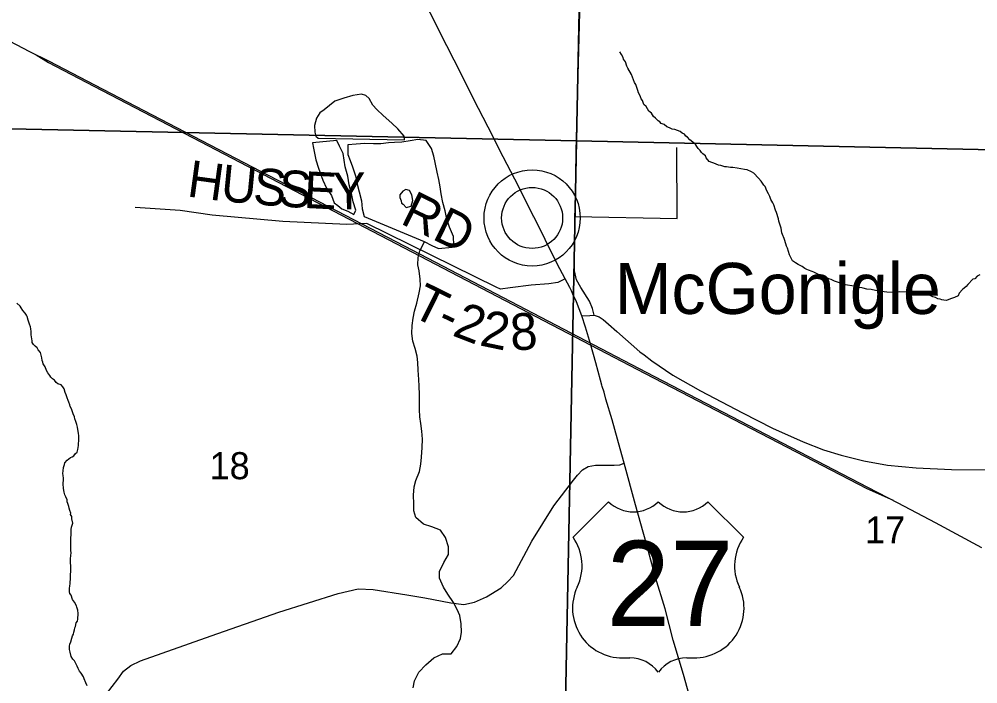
# Model space of a CAD drawing. Extents: x 0 to 34, y 0 to 22.
# Drawn here: x 6.13 to 7.614, y 14.792 to 15.821 of the extents above; entities that cross this region are included whole.
import ezdxf

# ---------------------------------------------------------------- set-up
doc = ezdxf.new("R2010")
doc.units = 0
for name, color, linetype in [('GM_X_County_Road', 7, 'Continuous'), ('GM_X_Minor_Lake', 7, 'Continuous'), ('GM_X_Minor_River', 7, 'Continuous'), ('GM_X_Rail_Line', 7, 'Continuous'), ('GM_X_Section', 7, 'Continuous'), ('GM_X_Section_Text', 7, 'Continuous'), ('GM_X_State_Route', 7, 'Continuous'), ('GM_X_Township_Road', 7, 'Continuous'), ('GM_X_Township_Road_Text', 7, 'Continuous'), ('GM_X_Unincorporated', 7, 'Continuous'), ('GM_X_Unincorporated_Location', 7, 'Continuous'), ('GM_X_Unincorporated_Text', 7, 'Continuous'), ('GM_X_US_Location', 7, 'Continuous'), ('GM_X_US_Route', 7, 'Continuous'), ('GM_X_US_Shield', 7, 'Continuous')]:
    doc.layers.add(name, color=color, linetype=linetype)

msp = doc.modelspace()

# ---------------------------------------------------------------- linework, layer by layer
at = {"layer": 'GM_X_County_Road'}
for points in [[(6.9899, 15.456), (6.9901, 15.4871), (6.9904, 15.5157), (6.9912, 15.5373), (6.9922, 15.6175), (6.9998, 15.8902), (7.0067, 16.3405), (7.0224, 16.9184), (7.0254, 17.1457)], [(7.0201, 15.3628), (7.0177, 15.3733), (7.0128, 15.3849), (6.9998, 15.4057), (6.993, 15.4175), (6.9897, 15.4318), (6.9899, 15.456)], [(6.2653, 14.7771), (6.2832, 14.7997), (6.2917, 14.8121), (6.3034, 14.8208), (6.318, 14.8278), (6.4275, 14.8668), (6.5322, 14.9031), (6.6241, 14.9321), (6.655, 14.9392), (6.6781, 14.9386), (6.7301, 14.9299), (6.7582, 14.9253), (6.7982, 14.9179), (6.8185, 14.9153), (6.8352, 14.9186), (6.8535, 14.9273), (6.8764, 14.941), (6.8868, 14.9508), (6.8953, 14.9601), (6.9238, 15.013), (6.9578, 15.0678), (6.9883, 15.1075), (6.9943, 15.1154), (7.0023, 15.1236), (7.0108, 15.1289), (7.0224, 15.1307), (7.0353, 15.1306), (7.0509, 15.1308), (7.06, 15.1311), (7.0665, 15.1341)]]:
    msp.add_lwpolyline(points, dxfattribs=at)
at = {"layer": 'GM_X_Minor_Lake'}
for points in [[(6.7265, 15.6345), (6.7262, 15.6398), (6.7166, 15.6514), (6.7069, 15.6603), (6.6938, 15.6719), (6.6837, 15.6812), (6.6778, 15.6882), (6.6722, 15.6982), (6.667, 15.7032), (6.6599, 15.7052), (6.6469, 15.7032), (6.6328, 15.6988), (6.619, 15.6941), (6.6106, 15.6875), (6.6021, 15.6808), (6.5956, 15.6763), (6.5905, 15.668), (6.5872, 15.6567), (6.5878, 15.6464), (6.5896, 15.6403), (6.593, 15.6369)], [(6.593, 15.6369), (6.7265, 15.6345)], [(6.6217, 15.6333), (6.5845, 15.6298), (6.5858, 15.6214), (6.5897, 15.6035), (6.5936, 15.5905), (6.6005, 15.5717), (6.606, 15.5595), (6.6137, 15.5483), (6.6177, 15.5369)], [(6.6177, 15.5369), (6.6233, 15.533), (6.6297, 15.5275), (6.6391, 15.5239), (6.6485, 15.5188), (6.6513, 15.5256), (6.6473, 15.5386), (6.6449, 15.5512), (6.641, 15.5646), (6.6389, 15.5783), (6.6347, 15.5928), (6.6316, 15.613), (6.6261, 15.6245), (6.6217, 15.6333)], [(6.757, 15.477), (6.7691, 15.4707), (6.7792, 15.4664), (6.8005, 15.4682), (6.8032, 15.4713), (6.8023, 15.485), (6.7965, 15.4991), (6.7922, 15.5117), (6.7894, 15.5243), (6.7862, 15.5373), (6.7834, 15.551), (6.7817, 15.5617), (6.78, 15.5731), (6.7772, 15.5842), (6.7741, 15.5995), (6.772, 15.609), (6.7684, 15.6212), (6.7603, 15.6335), (6.7474, 15.6349), (6.7356, 15.6328), (6.7226, 15.6308), (6.7112, 15.6302), (6.7017, 15.6296), (6.69, 15.6283), (6.6786, 15.6281), (6.6653, 15.6287), (6.652, 15.6278), (6.6391, 15.6265), (6.6392, 15.6117), (6.6428, 15.6022), (6.6464, 15.5926), (6.6511, 15.5788), (6.6528, 15.5678), (6.6567, 15.5537), (6.6599, 15.5399), (6.6612, 15.5277), (6.664, 15.5155)], [(6.7578, 15.4763), (6.757, 15.477), (6.7691, 15.4707), (6.7792, 15.4664), (6.8005, 15.4682), (6.8032, 15.4713), (6.8023, 15.485), (6.7965, 15.4991), (6.7922, 15.5117), (6.7894, 15.5243), (6.7862, 15.5373), (6.7834, 15.551), (6.7817, 15.5617), (6.78, 15.5731), (6.7772, 15.5842), (6.7741, 15.5995), (6.772, 15.609), (6.7684, 15.6212), (6.7603, 15.6335), (6.7474, 15.6349), (6.7356, 15.6328), (6.7226, 15.6308), (6.7112, 15.6302), (6.7017, 15.6296), (6.69, 15.6283), (6.6786, 15.6281), (6.6653, 15.6287), (6.652, 15.6278), (6.6391, 15.6265), (6.6392, 15.6117), (6.6428, 15.6022), (6.6464, 15.5926), (6.6511, 15.5788), (6.6528, 15.5678), (6.6567, 15.5537), (6.6599, 15.5399), (6.6612, 15.5277), (6.664, 15.5155)], [(6.7243, 15.5551), (6.7193, 15.5495), (6.7192, 15.5453), (6.7217, 15.54), (6.7221, 15.5365)], [(6.7221, 15.5365), (6.7247, 15.5346), (6.7295, 15.5296), (6.7372, 15.5317), (6.7396, 15.5404), (6.7382, 15.5492), (6.7342, 15.5561), (6.7289, 15.5573), (6.7243, 15.5551)], [(6.664, 15.5155), (6.757, 15.477)]]:
    msp.add_lwpolyline(points, dxfattribs=at)
at = {"layer": 'GM_X_Minor_River'}
for points in [[(7.2672, 15.5826), (7.2635, 15.5846), (7.2567, 15.5878), (7.2529, 15.5886), (7.2416, 15.5904), (7.2347, 15.5914), (7.2309, 15.5918), (7.2249, 15.5927), (7.2226, 15.5928), (7.2162, 15.5945), (7.2124, 15.5953), (7.2056, 15.5982), (7.2022, 15.5994), (7.1981, 15.6006), (7.1933, 15.6065), (7.1926, 15.6095), (7.1881, 15.6127), (7.1862, 15.615), (7.184, 15.6177), (7.181, 15.6208), (7.1792, 15.6239), (7.1777, 15.6266), (7.1755, 15.6286), (7.168, 15.6344), (7.1647, 15.6383), (7.1621, 15.6399), (7.1599, 15.643), (7.1561, 15.6446), (7.1535, 15.6473), (7.149, 15.649), (7.1448, 15.6506), (7.141, 15.6511), (7.1369, 15.6531), (7.1324, 15.6547), (7.1283, 15.6582), (7.1241, 15.6598), (7.1219, 15.6622), (7.1193, 15.6638), (7.1152, 15.668), (7.1122, 15.6704), (7.1089, 15.6754), (7.1048, 15.6786), (7.1004, 15.6859), (7.097, 15.689), (7.0949, 15.6952), (7.0927, 15.6979), (7.0913, 15.7025), (7.0887, 15.7071), (7.088, 15.7109), (7.0844, 15.7201), (7.0826, 15.7232), (7.0794, 15.7316), (7.078, 15.7355), (7.0725, 15.7451), (7.0706, 15.7486), (7.0685, 15.7551), (7.0656, 15.7593), (7.0649, 15.7616), (7.0627, 15.7662), (7.0601, 15.7705)], [(7.6169, 15.4253), (7.6131, 15.4235), (7.6095, 15.4194), (7.6061, 15.4187), (7.5983, 15.4106), (7.5956, 15.4076), (7.5925, 15.4046), (7.5902, 15.4028), (7.5851, 15.3972), (7.5835, 15.3931), (7.5777, 15.3906), (7.5716, 15.3881), (7.5681, 15.3866), (7.5647, 15.3859), (7.5612, 15.386), (7.5582, 15.3865), (7.5556, 15.3877), (7.5518, 15.3885), (7.5484, 15.3902), (7.5443, 15.3914), (7.539, 15.3942), (7.533, 15.3962), (7.5307, 15.3967), (7.5246, 15.3976), (7.5216, 15.398), (7.5178, 15.3985), (7.4923, 15.3991), (7.49, 15.3988), (7.4862, 15.3982), (7.4733, 15.3985), (7.4688, 15.399), (7.4657, 15.3998), (7.4612, 15.4003), (7.4555, 15.4012), (7.4487, 15.4025), (7.4422, 15.4034), (7.4366, 15.4047), (7.4343, 15.4051), (7.4294, 15.406), (7.4271, 15.4061), (7.4218, 15.4077), (7.4188, 15.4082), (7.4123, 15.4095), (7.4093, 15.4099), (7.404, 15.4116), (7.4014, 15.4124), (7.3923, 15.4157), (7.3867, 15.4181), (7.3833, 15.4193), (7.3761, 15.4222), (7.3739, 15.423), (7.3709, 15.425), (7.3671, 15.4262), (7.3603, 15.4298), (7.3577, 15.4306), (7.3516, 15.4327), (7.3494, 15.4338), (7.3464, 15.4351), (7.3423, 15.4382), (7.34, 15.4394), (7.3359, 15.4414), (7.3317, 15.4442), (7.3269, 15.4469), (7.3247, 15.4523), (7.3225, 15.4562), (7.3193, 15.4665), (7.3179, 15.4696), (7.315, 15.4784), (7.314, 15.4815), (7.3115, 15.488), (7.3108, 15.4903), (7.3094, 15.4979), (7.3083, 15.501), (7.3062, 15.5086), (7.3052, 15.5121), (7.3024, 15.522), (7.3009, 15.5255), (7.2984, 15.5339), (7.2966, 15.537), (7.2937, 15.542), (7.2919, 15.5466), (7.2897, 15.5509), (7.2872, 15.5555), (7.2846, 15.562), (7.2828, 15.5643), (7.2787, 15.5705), (7.2747, 15.5752), (7.2672, 15.5826)], [(6.7857, 14.8388), (6.799, 14.839), (6.8079, 14.8502), (6.8134, 14.8623), (6.8151, 14.8725), (6.8142, 14.8855), (6.8122, 14.898), (6.8082, 14.9076), (6.8023, 14.9183), (6.7938, 14.9314), (6.7872, 14.9422), (6.781, 14.956), (6.7808, 14.9662), (6.7875, 14.9802), (6.7949, 14.9926), (6.7948, 15.0044), (6.7901, 15.0189), (6.7823, 15.0301), (6.7688, 15.0352), (6.7559, 15.0396), (6.7444, 15.0497), (6.7411, 15.06), (6.7409, 15.0711), (6.7408, 15.0844), (6.7414, 15.0973), (6.7443, 15.1071), (6.7498, 15.1211), (6.7519, 15.1324), (6.7529, 15.1431), (6.7539, 15.1582), (6.7545, 15.1712), (6.7536, 15.1833), (6.7519, 15.1951), (6.7506, 15.2058), (6.75, 15.2172), (6.7499, 15.2279), (6.7501, 15.24), (6.7496, 15.2529), (6.749, 15.2636), (6.7477, 15.2781), (6.7472, 15.2895), (6.7462, 15.2994), (6.743, 15.3116), (6.7398, 15.3227), (6.7381, 15.3345), (6.7384, 15.347), (6.7401, 15.3584), (6.7422, 15.369), (6.7458, 15.3815), (6.7495, 15.3977), (6.7512, 15.4083), (6.7507, 15.4186), (6.7494, 15.4316), (6.7473, 15.4411), (6.7479, 15.4521), (6.7503, 15.4627), (6.7578, 15.4763)], [(6.2105, 15.0098), (6.2102, 15.0125), (6.2106, 15.0288), (6.211, 15.0311), (6.2115, 15.0349), (6.2132, 15.0413), (6.2118, 15.0478), (6.2119, 15.0512), (6.21, 15.0543), (6.2101, 15.0566), (6.209, 15.0608), (6.208, 15.0643), (6.2073, 15.0669), (6.2059, 15.0715), (6.2048, 15.0742), (6.2045, 15.0773), (6.2027, 15.0819), (6.2012, 15.0849), (6.1998, 15.0892), (6.1992, 15.0945), (6.1988, 15.0968), (6.1985, 15.0998), (6.1988, 15.1105), (6.1985, 15.115), (6.1982, 15.1177), (6.1983, 15.1223), (6.1988, 15.1272), (6.2004, 15.1317), (6.2012, 15.1344), (6.2044, 15.1385), (6.2098, 15.1425), (6.2125, 15.1436), (6.2148, 15.1454), (6.2175, 15.1488), (6.2202, 15.151), (6.2211, 15.1552), (6.2216, 15.1582), (6.222, 15.1612), (6.2221, 15.1642), (6.2225, 15.1684), (6.2227, 15.1768), (6.2224, 15.1798), (6.2217, 15.1833), (6.2214, 15.1859), (6.2207, 15.1894), (6.2197, 15.194), (6.2183, 15.1985), (6.2165, 15.2028), (6.2162, 15.2058), (6.214, 15.2101), (6.2115, 15.2181), (6.2093, 15.2216), (6.209, 15.2242), (6.2072, 15.2285), (6.2061, 15.2308), (6.2047, 15.235), (6.2029, 15.2396), (6.2015, 15.2434), (6.2001, 15.2492), (6.1978, 15.2519), (6.1953, 15.2554), (6.1903, 15.2566), (6.1874, 15.259), (6.1848, 15.2625), (6.1818, 15.2644), (6.1796, 15.2672), (6.1777, 15.2695), (6.1748, 15.2737), (6.1729, 15.2772), (6.1704, 15.283), (6.1675, 15.2876), (6.1668, 15.2903), (6.1661, 15.2926), (6.1654, 15.2972), (6.1633, 15.3052), (6.16, 15.3091), (6.1582, 15.3122), (6.1552, 15.3149), (6.1526, 15.3176), (6.1507, 15.3207), (6.1504, 15.3234), (6.1491, 15.3325), (6.1489, 15.3379), (6.1482, 15.3421), (6.1479, 15.3451), (6.1465, 15.3493), (6.1443, 15.3555), (6.1429, 15.3608), (6.1415, 15.3631), (6.1396, 15.3662), (6.1359, 15.3701), (6.1337, 15.3743), (6.1319, 15.3767), (6.127, 15.3817)], [(6.2355, 14.7895), (6.2337, 14.7938), (6.2312, 14.7999), (6.2297, 14.803), (6.2265, 14.8091), (6.2239, 14.8122), (6.2217, 14.8161), (6.2199, 14.8196), (6.2159, 14.828), (6.2133, 14.8304), (6.2107, 14.8346), (6.2093, 14.8415), (6.2083, 14.8457), (6.2084, 14.8506), (6.2089, 14.854), (6.2101, 14.8574), (6.2117, 14.8631), (6.213, 14.8669), (6.2142, 14.8695), (6.215, 14.8725), (6.2158, 14.8759), (6.2167, 14.8789), (6.2175, 14.8812), (6.2187, 14.8869), (6.2207, 14.8895), (6.2212, 14.8925), (6.2212, 14.8948), (6.2217, 14.899), (6.2217, 14.9012), (6.2211, 14.9066), (6.2197, 14.9108), (6.219, 14.9131), (6.2161, 14.9189), (6.2131, 14.9231), (6.2106, 14.9296), (6.2087, 14.932), (6.2084, 14.9346), (6.2082, 14.9407), (6.2086, 14.9438), (6.2091, 14.9475), (6.2092, 14.9506), (6.2096, 14.9536), (6.2101, 14.9745), (6.2099, 14.9802), (6.21, 14.9848), (6.2105, 14.992), (6.2106, 14.9943), (6.2103, 15), (6.2105, 15.0098)], [(6.7403, 14.786), (6.7421, 14.797), (6.7487, 14.8106), (6.7596, 14.8218), (6.7723, 14.8326), (6.7857, 14.8388)]]:
    msp.add_lwpolyline(points, dxfattribs=at)
at = {"layer": 'GM_X_Rail_Line'}
for points in [[(4.6429, 16.5543), (5.4558, 16.1314), (5.6881, 16.0106), (5.8718, 15.9147), (5.9787, 15.8592), (6.1465, 15.7709), (6.1767, 15.7561), (6.2472, 15.7195), (6.3997, 15.6402), (6.7392, 15.4634), (7.1004, 15.275), (7.4433, 15.0968), (7.4901, 15.0727), (7.5481, 15.0419), (7.6194, 15.0032)], [(6.1565, 15.766), (6.1756, 15.754), (6.2461, 15.7174), (6.3986, 15.6381), (6.7381, 15.4612), (7.0993, 15.2728), (7.4422, 15.0946), (7.4828, 15.0765)]]:
    msp.add_lwpolyline(points, dxfattribs=at)
at = {"layer": 'GM_X_Section'}
for points in [[(5.9708, 16.6629), (7.0136, 16.6391), (6.9929, 15.633), (5.9463, 15.655)], [(7.0136, 16.6391), (7.9916, 16.6192), (7.9729, 15.6119), (6.9929, 15.633)], [(6.9929, 15.633), (6.9732, 14.6315), (5.9159, 14.648), (5.9463, 15.655)], [(7.9729, 15.6119), (7.9542, 14.61), (6.9732, 14.6315), (6.9929, 15.633)]]:
    msp.add_lwpolyline(points, close=True, dxfattribs=at)
at = {"layer": 'GM_X_State_Route'}
for points in [[(7.0012, 15.362), (7.0137, 15.3627), (7.0201, 15.3628), (7.028, 15.3603), (7.0341, 15.3564), (7.0425, 15.3493), (7.0553, 15.3378), (7.0909, 15.3062), (7.0974, 15.3014)], [(7.0974, 15.3014), (7.1095, 15.2924), (7.1417, 15.2702), (7.1847, 15.2459), (7.2495, 15.2119), (7.296, 15.1881), (7.3438, 15.167), (7.3749, 15.1548), (7.4024, 15.1461), (7.4376, 15.1373), (7.4742, 15.1307), (7.5184, 15.1265), (7.5729, 15.1241), (7.6457, 15.1237)]]:
    msp.add_lwpolyline(points, dxfattribs=at)
at = {"layer": 'GM_X_Township_Road'}
for p, q in [((7.1488, 15.5125), (7.1483, 15.6225)), ((6.9904, 15.5157), (7.1488, 15.5125))]:
    msp.add_line(p, q, dxfattribs=at)
msp.add_lwpolyline([(6.9751, 15.4194), (6.964, 15.4137), (6.9501, 15.4113), (6.9225, 15.4094), (6.8904, 15.4055), (6.8753, 15.4032), (6.8683, 15.4064), (6.6684, 15.5048), (6.6375, 15.5031), (6.5386, 15.5079), (6.4291, 15.518), (6.3794, 15.525), (6.3101, 15.5296)], dxfattribs=at)
at = {"layer": 'GM_X_Unincorporated'}
for radius in [0.0744, 0.0472]:
    msp.add_circle((6.9242, 15.5135), radius, dxfattribs=at)
at = {"layer": 'GM_X_Unincorporated_Location'}
msp.add_line((6.9242, 15.5135), (6.9242, 15.5135), dxfattribs=at)
at = {"layer": 'GM_X_US_Route'}
for points in [[(6.9849, 15.4008), (6.9825, 15.4059), (6.9751, 15.4194), (6.963, 15.4425), (6.9446, 15.48), (6.9316, 15.5066), (6.9221, 15.5241), (6.9108, 15.5473), (6.8973, 15.5733), (6.8796, 15.6079), (6.8561, 15.654), (6.8335, 15.6979), (6.8148, 15.7355), (6.7921, 15.78), (6.7662, 15.8309), (6.7323, 15.8976), (6.7062, 15.9492), (6.7002, 15.9601)], [(7.0301, 15.2626), (7.0229, 15.2894), (7.0146, 15.3186), (7.007, 15.3443), (7.0012, 15.362), (6.993, 15.3834), (6.9874, 15.3957), (6.9849, 15.4008)], [(7.0328, 15.2527), (7.0322, 15.2547), (7.0301, 15.2626)], [(7.1707, 14.7625), (7.1584, 14.8069), (7.1424, 14.8601), (7.1302, 14.9086), (7.1149, 14.9568), (7.1005, 15.0107), (7.0843, 15.0692), (7.0665, 15.1341), (7.0604, 15.1563), (7.0481, 15.2009), (7.0383, 15.2332), (7.0355, 15.244), (7.0328, 15.2527)]]:
    msp.add_lwpolyline(points, dxfattribs=at)
at = {"layer": 'GM_X_US_Shield'}
for p, q in [((7.0425, 15.0743), (6.9876, 15.0193)), ((7.2513, 15.0193), (7.1963, 15.0743)), ((7.0645, 14.8326), (7.0755, 14.8326)), ((7.1634, 14.8326), (7.1744, 14.8326))]:
    msp.add_line(p, q, dxfattribs=at)
for centre, radius, start, end in [((7.081, 15.1135), 0.0549, 225.573, 314.427), ((7.1579, 15.1135), 0.0549, 225.573, 314.427), ((6.9246, 14.9752), 0.0769, 334.5471, 35.0009), ((7.3143, 14.9752), 0.0769, 144.9991, 205.4529), ((7.0636, 14.9095), 0.0769, 154.8319, 270.6383), ((7.1752, 14.9095), 0.0769, 269.3617, 25.1681), ((7.0755, 14.7776), 0.0549, 36.8699, 90), ((7.1634, 14.7776), 0.0549, 90, 143.1301)]:
    msp.add_arc(centre, radius, start, end, dxfattribs=at)

# ---------------------------------------------------------------- texts
at = {"layer": 'GM_X_Section_Text'}
for s, p in [('18', (6.4249, 15.1091)), ('17', (7.4394, 15.0097))]:
    msp.add_text(s, height=0.04186, rotation=0, dxfattribs=at).set_placement(p)
at = {"layer": 'GM_X_Township_Road_Text'}
for s, height, rotation, p in [('H', 0.0568, 352.195, (6.3888, 15.547)), ('U', 0.0568, 354.4714, (6.4408, 15.5399)), ('S', 0.0568, 354.9949, (6.4911, 15.5351)), ('S', 0.0568, 356.2884, (6.5307, 15.5316)), ('E', 0.0568, 357.1313, (6.5699, 15.5291)), ('Y', 0.0568, 0.2271, (6.6157, 15.5269)), ('RD', 0.05682, 333.878, (6.7184, 15.5058)), ('T', 0.0568, 333.5447, (6.7345, 15.3634)), ('2', 0.0568, 338.8146, (6.7989, 15.3321)), ('2', 0.0568, 348.1787, (6.8412, 15.3166)), ('-', 0.0568, 334.6589, (6.7737, 15.3439)), ('8', 0.0568, 3.1527, (6.8916, 15.3082))]:
    msp.add_text(s, height=height, rotation=rotation, dxfattribs=at).set_placement(p)
at = {"layer": 'GM_X_Unincorporated_Text'}
msp.add_text('McGonigle', height=0.07898, rotation=0, dxfattribs=at).set_placement((7.0519, 15.3649))
at = {"layer": 'GM_X_US_Location'}
for s in ['0', '/']:
    msp.add_text(s, height=0.000189, dxfattribs=at).set_placement((7.1194, 14.9469))
msp.add_text('27', height=0.000189, rotation=0, dxfattribs=at).set_placement((7.0803, 14.9077))
at = {"layer": 'GM_X_US_Shield'}
msp.add_text('27', height=0.13184, dxfattribs=at).set_placement((7.0395, 14.882))

doc.saveas('drawing.dxf')
